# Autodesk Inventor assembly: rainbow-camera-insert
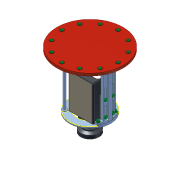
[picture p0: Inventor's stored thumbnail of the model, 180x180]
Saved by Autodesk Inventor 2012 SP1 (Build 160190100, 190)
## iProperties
Created: 2012-03
Part Number: rainbow-camera-insert
Document SubType Name: Assembly
Designer: jdh
Mass: 3567.45 g
Surface Area: 3765.29 cm^2
Volume: 2156.77 cm^3
Density: 1.65407 g/cm^3
Author: jdh
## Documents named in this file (14)
- C:\Documents and Settings\LACO\My Documents\Inventor\rainbow-camera-mount\01 assemblies\rainbow-camera-insert.iam
- C:\Documents and Settings\LACO\My Documents\Inventor\rainbow-camera-mount\02 parts\1503.ipt
- C:\Documents and Settings\LACO\My Documents\Inventor\rainbow-camera-mount\02 parts\8333T31.ipt
- C:\Documents and Settings\LACO\My Documents\Inventor\rainbow-camera-mount\02 parts\96551A790.ipt
- C:\Documents and Settings\LACO\My Documents\Inventor\rainbow-camera-mount\02 parts\92200A539.ipt
- C:\Documents and Settings\LACO\My Documents\Inventor\rainbow-camera-mount\02 parts\1505.ipt
- C:\Documents and Settings\LACO\My Documents\Inventor\rainbow-camera-mount\02 parts\1510.ipt
- C:\Documents and Settings\LACO\My Documents\Inventor\rainbow-camera-mount\02 parts\92200A537.ipt
- C:\Documents and Settings\LACO\My Documents\Inventor\rainbow-camera-mount\02 parts\1506.ipt
- C:\Documents and Settings\LACO\My Documents\Inventor\rainbow-camera-mount\02 parts\1508.ipt
- C:\Documents and Settings\LACO\My Documents\Inventor\rainbow-camera-mount\02 parts\1512.iam
- C:\Documents and Settings\LACO\My Documents\Inventor\Content Center Files\R2012\en-US\92949A537\92949A537-Default.ipt
- C:\Documents and Settings\LACO\My Documents\Inventor\rainbow-camera-mount\06 imports\FluxData\FD-1665.ipt
- C:\Documents and Settings\LACO\My Documents\Inventor\rainbow-camera-mount\06 imports\Sunex\Sunex Superfisheye.iam
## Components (70 placed, 13 different names)
1. 1503:1 — Mate:1, Tangent:1, Insert:1, Insert:2, Insert:3, Insert:4, Insert:5, Insert:6, Insert:7, Insert:8, Insert:9, Insert:10, Insert:11, Insert:12, Insert:25, Mate:3, Mate:6, Mate:7
2. 8333T31:1 — Mate:1, Tangent:1
3. 1505:1 — Insert:25, Mate:2, Mate:4, Mate:5, Insert:29, Insert:30, Insert:35, Insert:36, Insert:60, Insert:61
4. 1510:1 — Insert:29, Insert:30, Insert:31, Insert:32, Insert:37, Insert:38, Insert:41, Insert:42, Mate:11, Mate:12, Mate:13, Mate:14, Mate:15, Mate:16
5. 1506:1 — Insert:36, Insert:40
6. 1506:2 — Insert:35, Insert:39
7. 1508:1 — Insert:37, Insert:38, Insert:39, Insert:40, Insert:43, Insert:44
8. 1512:1 [sub-assembly] — Mate:11, Mate:12, Mate:17, Mate:18, Mate:19, Mate:20, Mate:21, Mate:22, Mate:23, Tangent:2, Insert:51, Insert:52, Insert:53
9. FD-1665:1 — Mate:21, Mate:22, Mate:23, Tangent:2, Insert:57
10. Sunex Superfisheye:1 [sub-assembly] — Insert:57
11. 96551A790:1 — Insert:1
12. 96551A790:2 — Insert:2
13. 96551A790:3 — Insert:3
14. 96551A790:4 — Insert:4
15. 96551A790:5 — Insert:5
16. 96551A790:6 — Insert:6
17. 96551A790:7 — Insert:7
18. 96551A790:8 — Insert:8
19. 96551A790:9 — Insert:9
20. 96551A790:10 — Insert:10
21. 96551A790:11 — Insert:11
22. 96551A790:12 — Insert:12
23. 92200A539:1
24. 92200A539:2
25. 92200A539:3
26. 92200A539:4
27. 92200A539:5
28. 92200A539:6
29. 92200A539:7
30. 92200A539:8
31. 92200A539:9
32. 92200A539:10
33. 92200A539:11
34. 92200A539:12
35. 96551A790:13 — Mate:2, Mate:3, Insert:27
36. 96551A790:14 — Mate:4, Mate:7, Insert:28
37. 96551A790:15 — Mate:5, Mate:6, Insert:26
38. 92200A537:1 — Insert:26
39. 92200A537:2 — Insert:27
40. 92200A537:3 — Insert:28
41. 96551A790:19 — Insert:42, Insert:45
42. 96551A790:18 — Insert:41, Insert:46
43. 92200A537:6 — Insert:45
44. 92200A537:7 — Insert:46
45. 96551A790:16 — Insert:31, Insert:33
46. 96551A790:17 — Insert:32, Insert:34
47. 92200A537:4 — Insert:34
48. 92200A537:5 — Insert:33
49. 96551A790:22 — Mate:13, Mate:17, Insert:48
50. 96551A790:23 — Mate:14, Mate:20, Insert:47
51. 96551A790:24 — Mate:15, Mate:18, Insert:50
52. 96551A790:25 — Mate:16, Mate:19, Insert:49
53. 92949A537 92949A537-Default:1 — Insert:47
54. 92949A537 92949A537-Default:2 — Insert:48
55. 92949A537 92949A537-Default:3 — Insert:49
56. 92949A537 92949A537-Default:4 — Insert:50
57. 96551A790:26 — Insert:51, Insert:54
58. 96551A790:27 — Insert:52, Insert:55
59. 96551A790:28 — Insert:53, Insert:56
60. 92949A537 92949A537-Default:5 — Insert:54
61. 92949A537 92949A537-Default:6 — Insert:55
62. 92949A537 92949A537-Default:7 — Insert:56
63. 92949A537 92949A537-Default:11 — Insert:63
64. 92949A537 92949A537-Default:10 — Insert:62
65. 96551A790:30 — Insert:61, Insert:63
66. 96551A790:29 — Insert:60, Insert:62
67. 92949A537 92949A537-Default:9 — Insert:59
68. 92949A537 92949A537-Default:8 — Insert:58
69. 96551A790:20 — Insert:43, Insert:58
70. 96551A790:21 — Insert:44, Insert:59
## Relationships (73: Insert 51, Mate 20, Tangent 2)
- Mate:1: 1503:1 ↔ 8333T31:1
- Tangent:1: 1503:1 ↔ 8333T31:1
- Insert:1: 1503:1 ↔ 96551A790:1
- Insert:2: 1503:1 ↔ 96551A790:2
- Insert:3: 1503:1 ↔ 96551A790:3
- Insert:4: 1503:1 ↔ 96551A790:4
- Insert:5: 1503:1 ↔ 96551A790:5
- Insert:6: 1503:1 ↔ 96551A790:6
- Insert:7: 1503:1 ↔ 96551A790:7
- Insert:8: 1503:1 ↔ 96551A790:8
- Insert:9: 1503:1 ↔ 96551A790:9
- Insert:10: 1503:1 ↔ 96551A790:10
- Insert:11: 1503:1 ↔ 96551A790:11
- Insert:12: 1503:1 ↔ 96551A790:12
- Insert:25: 1503:1 ↔ 1505:1
- Mate:2: 1505:1 ↔ 96551A790:13
- Mate:3: 1503:1 ↔ 96551A790:13
- Mate:4: 1505:1 ↔ 96551A790:14
- Mate:5: 1505:1 ↔ 96551A790:15
- Mate:6: 1503:1 ↔ 96551A790:15
- Mate:7: 1503:1 ↔ 96551A790:14
- Insert:26: 96551A790:15 ↔ 92200A537:1
- Insert:27: 96551A790:13 ↔ 92200A537:2
- Insert:28: 96551A790:14 ↔ 92200A537:3
- Insert:29: 1505:1 ↔ 1510:1
- Insert:30: 1505:1 ↔ 1510:1
- Insert:31: 1510:1 ↔ 96551A790:16
- Insert:32: 1510:1 ↔ 96551A790:17
- Insert:33: 96551A790:16 ↔ 92200A537:5
- Insert:34: 96551A790:17 ↔ 92200A537:4
- Insert:35: 1505:1 ↔ 1506:2
- Insert:36: 1505:1 ↔ 1506:1
- Insert:37: 1510:1 ↔ 1508:1
- Insert:38: 1510:1 ↔ 1508:1
- Insert:39: 1506:2 ↔ 1508:1
- Insert:40: 1506:1 ↔ 1508:1
- Insert:41: 1510:1 ↔ 96551A790:18
- Insert:42: 1510:1 ↔ 96551A790:19
- Insert:43: 1508:1 ↔ 96551A790:20
- Insert:44: 1508:1 ↔ 96551A790:21
- Insert:45: 96551A790:19 ↔ 92200A537:6
- Insert:46: 96551A790:18 ↔ 92200A537:7
- Mate:11: 1510:1 ↔ 1512:1
- Mate:12: 1510:1 ↔ 1512:1
- Mate:13: 1510:1 ↔ 96551A790:22
- Mate:14: 1510:1 ↔ 96551A790:23
- Mate:15: 1510:1 ↔ 96551A790:24
- Mate:16: 1510:1 ↔ 96551A790:25
- Mate:17: 1512:1 ↔ 96551A790:22
- Mate:18: 1512:1 ↔ 96551A790:24
- Mate:19: 1512:1 ↔ 96551A790:25
- Mate:20: 1512:1 ↔ 96551A790:23
- Insert:47: 96551A790:23 ↔ 92949A537 92949A537-Default:1
- Insert:48: 96551A790:22 ↔ 92949A537 92949A537-Default:2
- Insert:49: 96551A790:25 ↔ 92949A537 92949A537-Default:3
- Insert:50: 96551A790:24 ↔ 92949A537 92949A537-Default:4
- Mate:21: 1512:1 ↔ FD-1665:1
- Mate:22: 1512:1 ↔ FD-1665:1
- Mate:23: 1512:1 ↔ FD-1665:1
- Tangent:2: 1512:1 ↔ FD-1665:1
- Insert:51: 1512:1 ↔ 96551A790:26
- Insert:52: 1512:1 ↔ 96551A790:27
- Insert:53: 1512:1 ↔ 96551A790:28
- Insert:54: 96551A790:26 ↔ 92949A537 92949A537-Default:5
- Insert:55: 96551A790:27 ↔ 92949A537 92949A537-Default:6
- Insert:56: 96551A790:28 ↔ 92949A537 92949A537-Default:7
- Insert:57: FD-1665:1 ↔ Sunex Superfisheye:1
- Insert:58: 92949A537 92949A537-Default:8 ↔ 96551A790:20
- Insert:59: 92949A537 92949A537-Default:9 ↔ 96551A790:21
- Insert:60: 1505:1 ↔ 96551A790:29
- Insert:61: 1505:1 ↔ 96551A790:30
- Insert:62: 92949A537 92949A537-Default:10 ↔ 96551A790:29
- Insert:63: 92949A537 92949A537-Default:11 ↔ 96551A790:30
